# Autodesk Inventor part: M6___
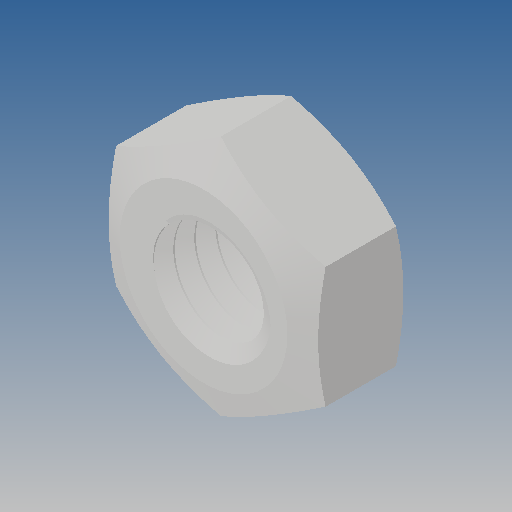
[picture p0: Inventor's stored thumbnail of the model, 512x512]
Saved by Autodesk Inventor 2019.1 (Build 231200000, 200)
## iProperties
Created: 2010-06
Part Number: M6___
Material: Ogólny
Document SubType Name: Modeling
Designer: CADENGINEERING4
Density: 1 g/cm^3
Appearance: Domyślna
Author: CADENGINEERING4
Revision Number: ANY
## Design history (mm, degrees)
feature "NONE"
node "Bryła1"
